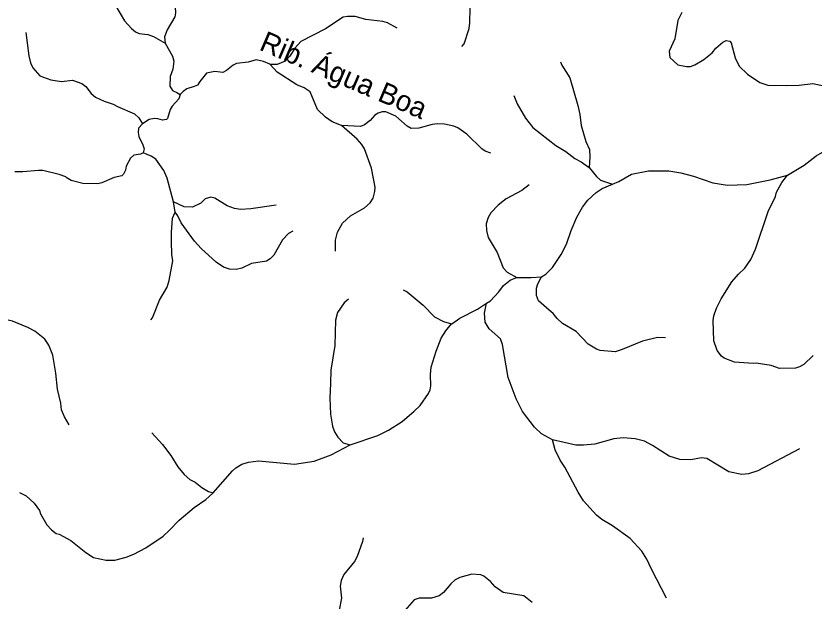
# Model space of a CAD drawing. Extents: x 500 to 555.2, y 9115.7 to 9171.
# Drawn here: x 543.19 to 549.39, y 9126.76 to 9131.3 of the extents above; entities that cross this region are included whole.
import ezdxf
from ezdxf.enums import TextEntityAlignment as Align

# ---------------------------------------------------------------- set-up
doc = ezdxf.new("R2010")
doc.units = 0
doc.header["$LTSCALE"] = 0.064
doc.layers.add('61', color=7, linetype='Continuous')
doc.layers.add('7', color=7, linetype='Continuous', lineweight=25)

msp = doc.modelspace()

# ---------------------------------------------------------------- linework, layer by layer
at = {"layer": '7'}
for points in [[(546.653, 9131.0664), (546.6694, 9131.0872), (546.7084, 9131.2072), (546.715, 9131.2512), (546.7218, 9131.5961), (546.7678, 9131.7065), (546.7868, 9131.7287), (546.8482, 9131.8395), (546.8629, 9131.8836), (546.8616, 9131.9485)], [(543.6272, 9131.6064), (543.6554, 9131.5842), (543.8157, 9131.5049), (543.9061, 9131.4395), (543.9644, 9131.3813), (544.031, 9131.267), (544.0853, 9131.2063), (544.1174, 9131.182), (544.1454, 9131.1691), (544.2126, 9131.1596), (544.258, 9131.1451), (544.3469, 9131.0926)], [(544.3993, 9131.4813), (544.4032, 9131.4462), (544.4246, 9131.3727), (544.4277, 9131.3289), (544.4219, 9131.2977), (544.362, 9131.1967), (544.3416, 9131.1423), (544.3469, 9131.0926)], [(548.3617, 9131.3315), (548.3306, 9131.2688), (548.3066, 9131.1262), (548.2636, 9131.0317), (548.2678, 9130.9817), (548.3297, 9130.9235), (548.3981, 9130.9106), (548.4278, 9130.9109), (548.4637, 9130.9237), (548.5329, 9130.9666), (548.5976, 9131.0184), (548.6264, 9131.0536), (548.6789, 9131.1011), (548.707, 9131.1139), (548.734, 9131.1081), (548.7459, 9131.0953), (548.7754, 9130.9795), (548.8082, 9130.9139), (548.8716, 9130.8519), (548.9683, 9130.7879), (549.0286, 9130.7679), (549.1782, 9130.763), (549.2734, 9130.7678), (549.3801, 9130.7809), (549.4648, 9130.761)], [(546.1497, 9131.2099), (546.0759, 9131.2498), (546.0378, 9131.2611), (545.9054, 9131.2763), (545.8228, 9131.2992), (545.7637, 9131.3009), (545.7313, 9131.2948), (545.5943, 9131.203), (545.4023, 9131.1065), (545.3562, 9131.056), (545.3131, 9130.9882), (545.2787, 9130.952), (545.2176, 9130.9266), (545.162, 9130.9277)], [(543.2659, 9131.1762), (543.289, 9130.9958), (543.3019, 9130.9394), (543.3191, 9130.9017), (543.374, 9130.8404), (543.4603, 9130.8091), (543.5428, 9130.7958), (543.6275, 9130.8055), (543.7003, 9130.7793), (543.7298, 9130.7564), (543.7734, 9130.7014), (543.8058, 9130.6741), (543.8747, 9130.643), (543.943, 9130.6202), (543.9766, 9130.601), (544.1103, 9130.5447), (544.1438, 9130.5143), (544.1707, 9130.467)], [(544.3469, 9131.0926), (544.4034, 9130.9919), (544.4138, 9130.9528), (544.4058, 9130.8923), (544.3862, 9130.8333), (544.3829, 9130.758), (544.4053, 9130.7242), (544.4393, 9130.7108), (544.4648, 9130.6934)], [(545.162, 9130.9277), (545.1608, 9130.929), (545.1102, 9130.9495), (545.0534, 9130.9627), (544.9928, 9130.9467), (544.9029, 9130.9345), (544.8748, 9130.9219), (544.8243, 9130.8798), (544.7954, 9130.865), (544.7343, 9130.8727), (544.6676, 9130.86), (544.618, 9130.7944), (544.5982, 9130.768), (544.5731, 9130.7576), (544.5166, 9130.7379), (544.4877, 9130.7186), (544.4648, 9130.6934)], [(547.4202, 9130.9482), (547.4302, 9130.9211), (547.4909, 9130.8235), (547.5547, 9130.6093), (547.5699, 9130.5387), (547.5796, 9130.4528), (547.617, 9130.3306), (547.6434, 9130.2675), (547.6468, 9130.2085), (547.6417, 9130.127)], [(545.7178, 9130.4539), (545.717, 9130.4539), (545.6452, 9130.4816), (545.5943, 9130.5173), (545.5322, 9130.5786), (545.4739, 9130.7161), (545.4286, 9130.7466), (545.3696, 9130.7682), (545.2176, 9130.8679), (545.162, 9130.9277)], [(544.4648, 9130.6934), (544.4524, 9130.6599), (544.4025, 9130.6047), (544.3875, 9130.5788), (544.3657, 9130.5086), (544.3577, 9130.5002), (544.3257, 9130.4939), (544.2898, 9130.5064), (544.2639, 9130.5085), (544.2224, 9130.4995), (544.1707, 9130.467)], [(547.0567, 9130.6855), (547.0812, 9130.6214), (547.1468, 9130.5104), (547.2037, 9130.437), (547.3837, 9130.2997), (547.4598, 9130.2527), (547.5299, 9130.1975), (547.5797, 9130.1728), (547.6417, 9130.127)], [(546.8783, 9130.2391), (546.833, 9130.2554), (546.8087, 9130.2725), (546.6904, 9130.387), (546.6216, 9130.4348), (546.59, 9130.4491), (546.5171, 9130.4644), (546.4625, 9130.4676), (546.4213, 9130.4623), (546.3188, 9130.4334), (546.2597, 9130.4301), (546.2264, 9130.448), (546.1394, 9130.5249), (546.0629, 9130.5608), (546.0322, 9130.5593), (546.002, 9130.5505), (545.9754, 9130.5331), (545.9392, 9130.4923), (545.8967, 9130.4591), (545.8654, 9130.4465), (545.7178, 9130.4539)], [(544.1707, 9130.467), (544.1401, 9130.4327), (544.1367, 9130.3981), (544.1416, 9130.3693), (544.1745, 9130.303), (544.1835, 9130.2724), (544.1776, 9130.2417)], [(545.6705, 9129.477), (545.672, 9129.5627), (545.686, 9129.6259), (545.7253, 9129.6944), (545.7873, 9129.7533), (545.8971, 9129.8152), (545.9401, 9129.8531), (545.9628, 9129.8891), (545.9767, 9129.9415), (545.9786, 9129.9756), (545.9508, 9130.1226), (545.8952, 9130.2736), (545.8761, 9130.3063), (545.8401, 9130.3486), (545.7178, 9130.4539)], [(549.1834, 9130.0687), (549.3117, 9130.1461), (549.4058, 9130.2171), (549.4714, 9130.2579), (549.5431, 9130.2921), (549.7005, 9130.3446), (549.7821, 9130.3616)], [(544.1776, 9130.2417), (544.1547, 9130.2313), (544.1049, 9130.2242), (544.0792, 9130.2002), (544.0446, 9130.1389), (544.038, 9130.1069), (544.0248, 9130.076), (544.0106, 9130.0631), (543.9502, 9130.0501), (543.8545, 9130.0084), (543.8234, 9130.0002), (543.7075, 9130.0034), (543.6163, 9130.0273), (543.5779, 9130.0493), (543.5749, 9130.056), (543.525, 9130.0744), (543.3959, 9130.1034), (543.3624, 9130.1051), (543.2419, 9130.0938), (543.1794, 9130.0953)], [(544.412, 9129.8608), (544.3624, 9130.0458), (544.3364, 9130.1041), (544.2743, 9130.1919), (544.2382, 9130.2167), (544.1776, 9130.2417)], [(547.6417, 9130.127), (547.6987, 9130.0581), (547.7301, 9130.0286), (547.8238, 9129.9979)], [(547.8238, 9129.9979), (547.873, 9130.0177), (547.971, 9130.0753), (548.1028, 9130.1019), (548.261, 9130.1018), (548.3548, 9130.0872), (548.4531, 9130.0609), (548.6014, 9130.0084), (548.7153, 9129.9905), (548.8666, 9129.9953), (549.0488, 9130.0324), (549.1834, 9130.0687)], [(549.3815, 9128.6678), (549.3095, 9128.5986), (549.276, 9128.5792), (549.2444, 9128.5699), (549.1204, 9128.5683), (549.0548, 9128.5893), (548.9383, 9128.6089), (548.9158, 9128.6061), (548.7719, 9128.6158), (548.6912, 9128.6481), (548.6703, 9128.6619), (548.6359, 9128.7059), (548.6095, 9128.7827), (548.6048, 9128.9402), (548.6109, 9128.9771), (548.6302, 9129.036), (548.6662, 9129.109), (548.7507, 9129.2407), (548.8016, 9129.2997), (548.852, 9129.3452), (548.8977, 9129.4134), (548.9346, 9129.4939), (549.0314, 9129.7853), (549.0896, 9129.9022), (549.0973, 9129.9371), (549.1381, 9130.0118), (549.1834, 9130.0687)], [(547.1767, 9129.9933), (547.1191, 9129.9503), (546.9978, 9129.8856), (546.9345, 9129.8357), (546.8769, 9129.7759), (546.8576, 9129.7389), (546.8415, 9129.6901), (546.843, 9129.6383), (546.8572, 9129.5855), (546.9267, 9129.4671), (546.973, 9129.3487), (547.0043, 9129.3142), (547.0786, 9129.2728)], [(547.2707, 9129.2788), (547.3061, 9129.3002), (547.3557, 9129.3518), (547.4234, 9129.4534), (547.4647, 9129.5328), (547.5014, 9129.6391), (547.5449, 9129.742), (547.5907, 9129.8209), (547.6321, 9129.8738), (547.6956, 9129.9341), (547.7423, 9129.965), (547.8238, 9129.9979)], [(545.2109, 9129.8354), (545.0138, 9129.808), (544.9333, 9129.8019), (544.8852, 9129.8098), (544.8297, 9129.8301), (544.7336, 9129.8886), (544.7014, 9129.8968), (544.6582, 9129.8846), (544.6237, 9129.851), (544.561, 9129.8195), (544.4949, 9129.8231), (544.412, 9129.8608)], [(544.4254, 9129.7796), (544.425, 9129.7802), (544.412, 9129.8608)], [(544.2354, 9128.9449), (544.248, 9128.9618), (544.3039, 9129.0966), (544.3627, 9129.1982), (544.3791, 9129.2499), (544.4071, 9129.4042), (544.3991, 9129.4534), (544.3962, 9129.5542), (544.3962, 9129.6226), (544.4035, 9129.7346), (544.4254, 9129.7796)], [(545.3389, 9129.6332), (545.3061, 9129.6142), (545.2601, 9129.5656), (545.1909, 9129.447), (545.1627, 9129.4187), (545.1349, 9129.4), (545.0192, 9129.3817), (544.9441, 9129.3469), (544.8983, 9129.336), (544.8473, 9129.3395), (544.7994, 9129.354), (544.744, 9129.3929), (544.6278, 9129.499), (544.5746, 9129.5557), (544.4719, 9129.6975), (544.4451, 9129.7536), (544.4254, 9129.7796)], [(543.6012, 9128.1295), (543.5648, 9128.1932), (543.5431, 9128.2456), (543.5363, 9128.2987), (543.5098, 9128.406), (543.4969, 9128.5316), (543.4737, 9128.6705), (543.4445, 9128.7481), (543.4119, 9128.7941), (543.3338, 9128.8561), (543.2799, 9128.8866), (543.1615, 9128.9343), (543.0829, 9128.9523), (543.0262, 9128.9783), (542.8282, 9129.1353), (542.6942, 9129.201), (542.6371, 9129.2365), (542.3153, 9129.4705)], [(546.8448, 9129.0733), (546.8762, 9129.0935), (546.9406, 9129.1626), (546.9755, 9129.2107), (547.0269, 9129.2537), (547.0773, 9129.2728), (547.0786, 9129.2728)], [(547.0786, 9129.2728), (547.1904, 9129.2745), (547.2707, 9129.2788)], [(548.2357, 9128.8046), (548.1723, 9128.8077), (548.0554, 9128.7803), (547.8987, 9128.7135), (547.8431, 9128.6962), (547.7261, 9128.7077), (547.6989, 9128.7177), (547.6328, 9128.756), (547.5414, 9128.8552), (547.4356, 9128.9174), (547.3927, 9128.9554), (547.3628, 9128.9952), (547.3297, 9129.0198), (547.2485, 9129.0917), (547.2335, 9129.1331), (547.2335, 9129.1919), (547.2436, 9129.2249), (547.2707, 9129.2788)], [(546.1968, 9129.1778), (546.2266, 9129.1633), (546.352, 9129.0593), (546.4397, 9128.9686), (546.5095, 9128.9319), (546.5732, 9128.9131)], [(545.7718, 9129.1048), (545.7377, 9129.0766), (545.686, 9129.0026), (545.671, 9128.9431), (545.6652, 9128.7453), (545.6344, 9128.5531), (545.6312, 9128.453), (545.6279, 9128.3362), (545.6314, 9128.2139), (545.6487, 9128.12), (545.664, 9128.0756), (545.6899, 9128.0336), (545.7301, 9127.99), (545.7856, 9127.9748)], [(546.5732, 9128.9131), (546.5739, 9128.9139), (546.6369, 9128.9578), (546.7734, 9129.0273), (546.8448, 9129.0733)], [(547.3577, 9128.0122), (547.2723, 9128.0602), (547.2166, 9128.1126), (547.1245, 9128.2323), (547.0734, 9128.3306), (547.0119, 9128.4967), (546.9695, 9128.7546), (546.9532, 9128.7983), (546.8651, 9128.8761), (546.8331, 9128.9271), (546.8296, 9128.9962), (546.8448, 9129.0733)], [(545.7856, 9127.9748), (546.0005, 9128.0468), (546.0831, 9128.0873), (546.1881, 9128.1562), (546.2815, 9128.2348), (546.3275, 9128.2807), (546.3933, 9128.3739), (546.4068, 9128.4016), (546.4119, 9128.4316), (546.4101, 9128.5205), (546.415, 9128.578), (546.4524, 9128.7021), (546.4928, 9128.8024), (546.5271, 9128.8608), (546.5732, 9128.9131)], [(544.2429, 9128.0685), (544.3268, 9127.9777), (544.3908, 9127.8924), (544.4446, 9127.8044), (544.4954, 9127.7436), (544.5381, 9127.7058), (544.5794, 9127.684), (544.6315, 9127.6434), (544.6845, 9127.612), (544.7202, 9127.6018)], [(549.2764, 9127.9428), (548.952, 9127.7725), (548.8789, 9127.7497), (548.8266, 9127.7448), (548.726, 9127.7639), (548.5556, 9127.8676), (548.5149, 9127.8726), (548.4307, 9127.858), (548.3463, 9127.8608), (548.2633, 9127.8864), (548.1345, 9127.9691), (548.0707, 9128.0027), (547.9985, 9128.0219), (547.9065, 9128.0286), (547.8345, 9128.0204), (547.6856, 9127.9808), (547.5983, 9127.9712), (547.5379, 9127.9713), (547.3577, 9128.0122)], [(544.7202, 9127.6018), (544.8703, 9127.773), (544.8972, 9127.7964), (544.9437, 9127.8235), (544.9961, 9127.8399), (545.0724, 9127.8496), (545.353, 9127.8235), (545.5052, 9127.8483), (545.6364, 9127.8976), (545.7856, 9127.9748)], [(548.2421, 9126.7846), (548.1248, 9127.0087), (548.0899, 9127.0881), (548.051, 9127.1488), (547.959, 9127.247), (547.8223, 9127.3462), (547.7404, 9127.3938), (547.6981, 9127.4294), (547.5986, 9127.5403), (547.5553, 9127.6065), (547.4529, 9127.8017), (547.4153, 9127.8552), (547.378, 9127.9345), (547.3577, 9128.0122)], [(543.2153, 9127.6042), (543.2672, 9127.5774), (543.3294, 9127.5206), (543.3717, 9127.4646), (543.3791, 9127.4395), (543.4286, 9127.3536), (543.4637, 9127.3154), (543.5018, 9127.2863), (543.524, 9127.2802), (543.6145, 9127.2316), (543.7306, 9127.1397), (543.7906, 9127.0995), (543.8899, 9127.079), (543.9556, 9127.0789), (544.0441, 9127.1015), (544.1032, 9127.1245), (544.1978, 9127.1743), (544.3314, 9127.2664), (544.3821, 9127.3113), (544.4566, 9127.3894), (544.5719, 9127.4892), (544.6626, 9127.5509), (544.7185, 9127.5998), (544.7202, 9127.6018)], [(545.8851, 9127.2525), (545.8815, 9127.2243), (545.8395, 9127.1089), (545.8179, 9127.0692), (545.7353, 9126.9673), (545.7149, 9126.9224), (545.7079, 9126.8784), (545.7177, 9126.7836), (545.6995, 9126.6906), (545.6802, 9126.6411)], [(547.1995, 9126.7518), (547.1334, 9126.8031), (546.9744, 9126.828), (546.9116, 9126.8732), (546.8742, 9126.9148), (546.8227, 9126.9544), (546.7988, 9126.9654), (546.7311, 9126.9706), (546.6379, 9126.9448), (546.601, 9126.9265), (546.5671, 9126.8961), (546.5095, 9126.8291), (546.476, 9126.8027), (546.4173, 9126.7854), (546.3197, 9126.7837), (546.2828, 9126.7705), (546.1902, 9126.6688)]]:
    msp.add_lwpolyline(points, dxfattribs=at)

# ---------------------------------------------------------------- texts
at = {"layer": '61'}
msp.add_text('Rib. Água Boa', height=0.16, rotation=336.801, dxfattribs=at).set_placement((545.7044, 9130.7725), align=Align.CENTER)

doc.saveas('drawing.dxf')
